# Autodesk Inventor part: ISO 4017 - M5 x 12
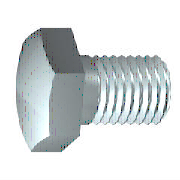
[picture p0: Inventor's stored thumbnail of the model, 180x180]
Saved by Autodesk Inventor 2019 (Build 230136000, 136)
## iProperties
IsCustomPart: 0
Created: 2018-01
Part Number: ISO 4017 - M5 x 12
Material: Acier inoxydable 440C
Description: Vis à tête hexagonale
Document SubType Name: Modeling
Standard: ISO 4017
Designer: Thier
Standard Revision: Fourth edition 2011-04-01
Standards Organization: ISO
Language: fr-FR
Size Designation: M5 x 12
Categories: <MemberInstance><Categories><Category DisplayName="Visserie" InternalName="e4da775c-781d-43d5-af7c-5136215cf5a6" Mnemonic="FSTN"><Category DisplayName="Vis" Int
Density: 7.75 g/cm^3
Appearance: Semi-poli
Author: Thier
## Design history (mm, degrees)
sketch "Esquisse1"
  geometry: L1 (0, 3.44)-(0, 2.5); L2 (2.4, 2.5)-(12, 2.5); L3 (12, 2.5)-(12, 0); L4 (12, 0)-(-0.5, 0); L5 (-3, 0)-(14.5, 0) reference; L6 (-0.5, 0)-(-0.5, 3.44); L7 (-0.5, 3.44)-(0, 3.44); L8 (2.4, 2.5)-(1.909, 2.5); L9 (1.909, 2.5)-(0, 2.5); L10 (0, -0.688)-(0, 4.128) reference
  constraints: 16 end point, 2 collinear, 2 perpendicular, 1 parallel
  dimensions: "d0" = 12 distance between parallel lines of L3 L1 (= NLG); "d1" = 9.6 distance from line of L2.start L3 (= GEL); "d2" = 5 diameter of L2 L4 (= GD); "d9" = 0.5001 distance between parallel lines of L6 L1 (computed from SD); "d10" = 6.88 diameter of L7 L4 (= SD2); "d13" = 0.49086 distance of L2.start L8.end (computed from GAL); "d14" = 5 diameter of L9 L4 (= BDM)
revolve "Corps" sketch "Esquisse1" stored, may be unused: angle "d12" = 90 deg
sketch "Esquisse2"
  geometry: L1 (0, 4.619)-(4, 2.309); L2 (4, 2.309)-(4, -2.309); L3 (4, -2.309)-(0, -4.619); L4 (0, -4.619)-(-4, -2.309); L5 (-4, -2.309)-(-4, 2.309); L6 (-4, 2.309)-(0, 4.619); 2 further points
  constraints: 12 end point, 1 coincident, 1 vertical, 11 other
  dimensions: "d11" = 8 distance between parallel lines of L5 L2 (= SW)
extrude "Tête" join sketch "Esquisse2" distance "d3" = 3 (= KOH - SD); taper "d4" = 0 deg
sketch "Esquisse4"
  geometry: L1 (-3.5, 4)-(-3.5, 4.619); L2 (-3.5, 4.619)-(-3.143, 4.619); L3 (-3.143, 4.619)-(-3.5, 4); L4 (-4.1, 0)-(0.1, 0) reference; L5 (-0.5, 4.619)-(-3.5, 4.619) reference; L6 (-3.5, 2.309)-(-3.5, 4.619) reference
  constraints: 6 end point, 2 collinear, 1 perpendicular, 1 vertical
  dimensions: "d5" = 30 deg angle of L3 L1 (= ANG1); "d19" = 8 diameter of L1.start L4 (= SW0)
revolve "Chanfrein1" sketch "Esquisse4" stored, may be unused: angle "d21" = 90 deg
workplane "Work Plane1"
body "Solid1"
feature "Filetage" dims "d15" = 9.6 (= GEL), "d16" = 0
chamfer "Chanfrein2" distance "d6" = 0.49076 (= -0.5 x SPD + 0.5 x GD); stored, may be unused: second distance "d7" = 0.49086 (computed from GUL), angle "d55" = 45 deg
other parameters: "NLG" = 12 [user parameter; used in 1 equation term], "GD" = 5 (= NND) [user parameter; used in 2 equation terms], "BDM" = 5 (= NND) [user parameter; used in 1 equation term], "KOH" = 3.5 [user parameter; used in 1 equation term], "GEL" = 9.6 [user parameter; used in 2 equation terms], "SW" = 8 [user parameter; used in 2 equation terms], "SW0" = 8 (= SW) [user parameter; used in 1 equation term], "SPD" = 4.01848 (= NND - 1.2269 x PTC) [user parameter; used in 1 equation term], "SD2" = 6.88 [user parameter; used in 2 equation terms], "SD" = 0.5 [user parameter; used in 2 equation terms], "ANG1" = 30 deg [user parameter; used in 1 equation term], "GAL" = 0.49076 (= 0.61345 x PTC) [user parameter; used in 1 equation term], "GUL" = 0.49076 (= 0.61345 x PTC) [user parameter; used in 1 equation term], "d8" = 0, "RR" = 0.2 [user parameter], "d57" = 0, "d58" = 0, "TPU" = 12.5 (computed from PTC) [user parameter], "GD1" = 4.01848 (= THREADDIA - 1.2269 x PTC) [user parameter], "THREADDIA" = 5 [user parameter; used in 1 equation term], "SDH" = 6.88 (= SD2) [user parameter], "SDHG" = 2.4 [user parameter], "TOA" = 30 deg [user parameter], "PTC" = 0.8 [user parameter; used in 5 equation terms], "NND" = 5 [user parameter; used in 3 equation terms], "E0" = 9.24 [user parameter]
